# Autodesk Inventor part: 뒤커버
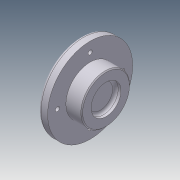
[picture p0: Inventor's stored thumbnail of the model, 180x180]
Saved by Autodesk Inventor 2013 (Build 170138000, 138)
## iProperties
Company: 한국ATC센터
Created: 2014-11
Part Number: 뒤커버
Document SubType Name: Modeling
Designer: KYOUNG IL JANG
Density: 2.71 g/cm^3
Material: Aluminum-6061
Mass: 280.898 g
Surface Area: 198.677 cm^2
Volume: 103.653 cm^3
Author: KYOUNG IL JANG
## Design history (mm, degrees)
revolve "회전1" stored, may be unused: angle "d4" = 90 deg
sketch "스케치2"
  geometry: 2 further points
  constraints: 1 vertical alignment
  dimensions: "d14" = 35 distance of point (0, 0) point (0, 35)
hole "구멍2" sketch "스케치2" diameter "d15" = 4.5; stored, may be unused: countersink angle "d19" = 90 deg, drill point angle "d21" = 118 deg; dims "d16" = 6, "d17" = 8, "d18" = 4.4, "d20" = 8
fillet "모깎기1" dims "d29" = 3
chamfer "모따기2" distance "d30" = 1; stored, may be unused: second distance "d31" = 2, angle "d32" = 30 deg
sketch "스케치3"
  geometry: L1 (-22.444, 6.652)-(-10, 14.967); L2 (-22.444, -6.652)-(-10, -14.967); L3 (10, -14.967)-(22.444, -6.652); L4 (22.444, 6.652)-(10, 14.967); A1 r 18 centre (0, 0) between (-18, 0) and (18, 0); A2 r 8 centre (18, 0) between (22.444, -6.652) and (22.444, 6.652); A3 r 8 centre (-18, 0) between (-22.444, 6.652) and (-22.444, -6.652); 1 further point
  constraints: 10 point on circle, 8 end point, 6 tangent, 3 centre point, 2 horizontal alignment, 2 parallel, 1 coincident, 1 equal radius
  dimensions: "d36" = 36 diameter of A1; "d37" = 16 diameter of A2
extrude "돌출1" join sketch "스케치3" distance "d38" = 7; taper "d39" = 0 deg
hole "구멍3" diameter "d43" = 32; stored, may be unused: countersink angle "d47" = 90 deg, drill point angle "d49" = 0 deg; dims "d41" = 10, "d42" = 10, "d44" = 6, "d45" = 4, "d46" = 2, "d48" = 6
fillet "모깎기2" dims "d40" = 3
node "솔리드1"
pattern_circular "원형 패턴2" dims angle "d34" = 360 deg
sketch "스케치1"
  geometry: L1 (-13.5, 0)-(13.5, 0); L2 (-13.5, 0)-(-13.5, 45.5); L3 (-13.5, 45.5)-(-3.5, 45.5); L4 (-3.5, 45.5)-(-3.5, 26); L5 (-3.5, 26)-(13.5, 26); L6 (13.5, 26)-(13.5, 0); 2 further points
  constraints: 12 end point, 3 parallel, 2 perpendicular, 1 coincident, 1 horizontal, 1 midpoint
  dimensions: "d0" = 27 distance of L1.start L1.end; "d1" = 91 diameter of L3 L1; "d2" = 52 diameter of L5 L1; "d3" = 10 distance of L2.end L3.end
